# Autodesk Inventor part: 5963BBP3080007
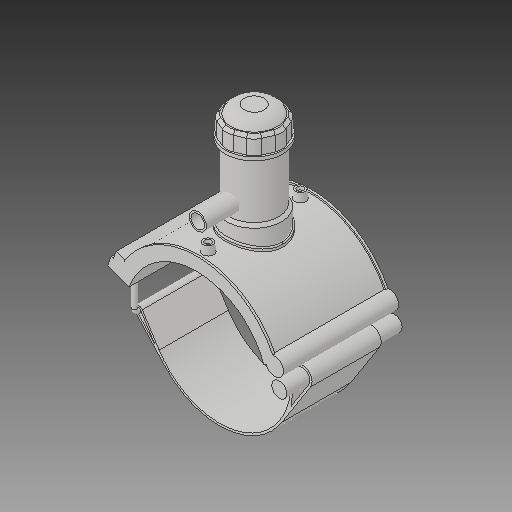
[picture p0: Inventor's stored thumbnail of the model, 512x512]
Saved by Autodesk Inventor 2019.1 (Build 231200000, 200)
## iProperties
Created: 2017-07
Part Number: 5963BBP3080007
Material: Generic
Description: PLASSON TAPPING SADDLE 8''IPS x 3/4''IPS
Document SubType Name: Modeling
Designer: KIM
Density: 1 g/cm^3
Appearance: Default
Author: KIM
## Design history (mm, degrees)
derived "5963BBP_5963BUP.ipt"
feature "Solid1::5963BBP_5963BUP.ipt"
feature "Solid2::5963BBP_5963BUP.ipt"
feature "Solid3::5963BBP_5963BUP.ipt"
tag "TaggingFeature1"
body "Solid1"
body "Solid2"
body "Solid3"
other parameters: "d_" = 218.7, "B_" = 179.832, "L_" = 176.022, "d_t" = 6, "H_2" = 177.038, "H_1" = 65.024, "d_1" = 26.6, "H_" = 86.106, "d1" = 253.692, "d148" = 3.2805, "d160" = 3.2805, "d169" = 3.2805, "d192" = 6.9984, "d0" = 218.7, "d2" = 269.748, "d3" = 54.675, "d4" = 176.022, "d5" = 0, "d6" = 0.1, "d8" = 0, "d19" = 6, "d20" = 6, "d21" = 105.6132, "d23" = 0, "d24" = 52.8066, "d26" = 0, "d27" = 3, "d28" = 3, "d29" = 3, "d30" = 72.9, "d31" = 6, "d32" = 0, "d33" = 0, "d34" = 0.6, "d40" = 131.91984, "d41" = 87.48, "d43" = 0, "d45" = 0, "d47" = 232.4592, "d70" = 15, "d72" = 0, "d73" = 6, "d75" = 5, "d76" = 0, "d77" = 10.935, "d78" = 139.35, "d79" = 15, "d80" = 70.4088, "d82" = 5 deg, "d84" = 4, "d85" = 14, "d86" = 0, "d87" = 3, "d88" = 0, "d89" = 1, "d90" = 1, "d91" = 140.8176, "d92" = 0, "d93" = 0.5, "d94" = 115.10526, "d96" = 258.76584, "d97" = 3.52044, "d98" = 0, "d102" = 2.187, "d120" = 140 deg, "d121" = 24.228, "d122" = 20 deg, "d123" = 507.384, "d124" = 152.2152, "d126" = 0, "d143" = 225.261, "d145" = 26.91692, "d149" = 3.2805, "d150" = 29.60862, "d153" = 176.022, "d154" = 0, "d156" = 126.846, "d157" = 160 deg, "d159" = 6.9984, "d161" = 3.2805, "d162" = 105.6132, "d163" = 0, "d164" = 109.35, "d167" = 21.87, "d168" = 123.7522, "d170" = 3.2805, "d172" = 0, "d173" = 1, "d175" = 109.35, "d176" = 20 deg, "d177" = 15.309, "d178" = 34.992, "d180" = 0, "d183" = 13.9968, "d184" = 12.2472, "d185" = 57.20715, "d186" = 57.20715, "d187" = 126.846, "d188" = 10.4976, "d189" = 15.309, "d190" = 0, "d191" = 190.269, "d193" = 6.9984, "d194" = 6.16077, "d195" = 90 deg, "d197" = 0, "d199" = 0, "d200" = 17.496, "d202" = 0, "d203" = 177.038, "d204" = 83.106, "d205" = 61.236, "d206" = 74.358, "d207" = 132.7785, "d208" = 138.08964, "d209" = 164.64534, "d210" = 75.2328, "d211" = 87.48, "d212" = 69.984, "d213" = 46.5516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
